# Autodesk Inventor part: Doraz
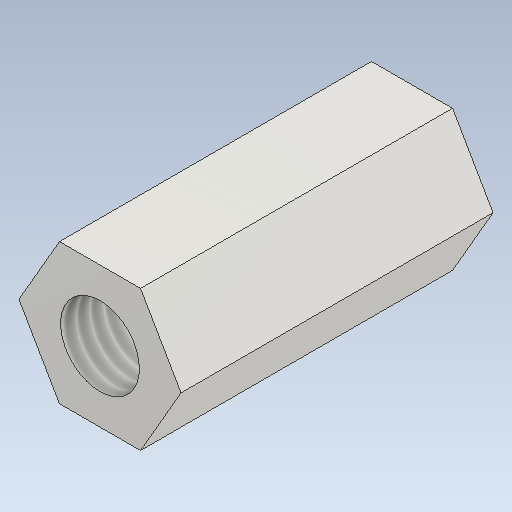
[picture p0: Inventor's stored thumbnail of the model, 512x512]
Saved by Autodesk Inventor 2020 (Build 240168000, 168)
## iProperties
Created: 2025-03
Part Number: Doraz
Material: Ocel
Document SubType Name: Modeling
Designer: doma
Density: 7.85 g/cm^3
Appearance: Ocel
Mass: 69.8377 g
Surface Area: 39.5767 cm^2
Volume: 8.89653 cm^3
Author: doma
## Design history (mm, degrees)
sketch "Náčrt1"
  geometry: L1 (5.196, 9)-(10.392, 0); L2 (10.392, 0)-(5.196, -9); L3 (5.196, -9)-(-5.196, -9); L4 (-5.196, -9)-(-10.392, 0); L5 (-10.392, 0)-(-5.196, 9); L6 (-5.196, 9)-(5.196, 9); 2 further points
  constraints: 12 end point, 1 coincident, 13 other
  dimensions: "d0" = 18 distance between parallel lines of L3 L6
extrude "Vysunutí1" new body sketch "Náčrt1" distance "d1" = 40; taper "d2" = 0 deg
sketch "Náčrt2"
  geometry: 2 further points
  constraints: 1 coincident
hole "Díra1" sketch "Náčrt2" at (0, 0) diameter "d3" = 10.106; stored, may be unused: countersink angle "d7" = 90 deg, drill point angle "d9" = 118 deg; dims "d4" = 20, "d5" = 4, "d6" = 2, "d8" = 28
node "Těleso1"
